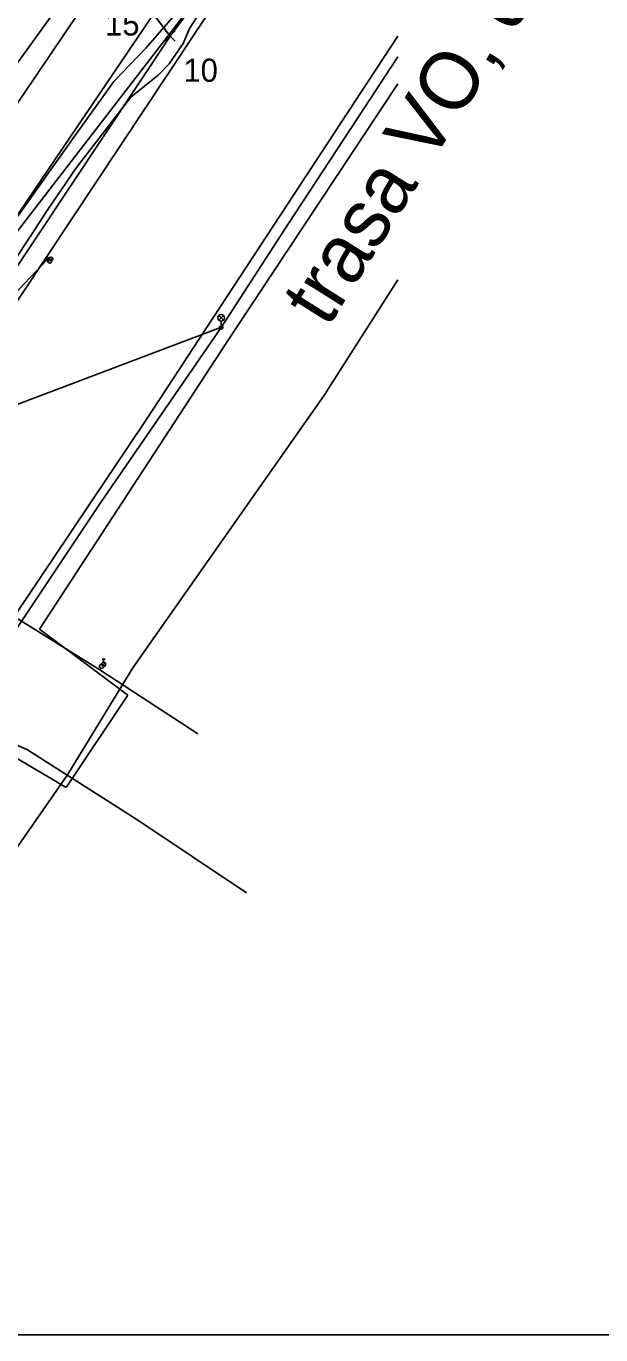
# Model space of a CAD drawing. Extents: x -263861 to -263441, y -1242367 to -1242070.
# Drawn here: x -263782.2 to -263732.4, y -1242367.2 to -1242254.1 of the extents above; entities that cross this region are included whole.
import ezdxf

# ---------------------------------------------------------------- set-up
doc = ezdxf.new("R2010")
doc.units = 0
for name, color, linetype in [('KFA_BODY', 7, 'Continuous'), ('KFA_JESTV_IS_DSP', 7, 'Continuous'), ('KFA_SITUACIA_DSP', 7, 'Continuous'), ('KFA_VO_prelozka_pri_vjazde_do KFA_TRASA', 7, 'Continuous'), ('POPIS', 7, 'Continuous'), ('RAM_NA_TLAC_A3_1-1000', 7, 'Continuous')]:
    doc.layers.add(name, color=color, linetype=linetype)

msp = doc.modelspace()

# ---------------------------------------------------------------- linework, layer by layer
at = {"layer": 'KFA_BODY'}
for p, q in [((-263770.14, -1242255.37), (-263769.26, -1242254.48)), ((-263769.26, -1242255.37), (-263770.14, -1242254.48)), ((-263769.7, -1242254.93), (-263769.7, -1242254.93))]:
    msp.add_line(p, q, dxfattribs=at)
at = {"layer": 'KFA_JESTV_IS_DSP'}
for p, q in [((-263806.91, -1242290.43), (-263750, -1242211.71)), ((-263766.13, -1242251.37), (-263768.04, -1242254.28)), ((-263771.82, -1242255.98), (-263768.68, -1242252.39)), ((-263768.04, -1242254.28), (-263768.58, -1242255.58)), ((-263750, -1242254.94), (-263754.37, -1242261.56)), ((-263774.57, -1242258.86), (-263771.82, -1242255.98)), ((-263768.58, -1242255.58), (-263769.79, -1242257.33)), ((-263769.79, -1242257.33), (-263770.75, -1242258.31)), ((-263750, -1242256.71), (-263759.47, -1242271.14)), ((-263777.94, -1242263.54), (-263774.57, -1242258.86)), ((-263770.75, -1242258.31), (-263773.12, -1242260.22)), ((-263764.86, -1242281.49), (-263750, -1242259.06)), ((-263773.12, -1242260.22), (-263777.8, -1242266.3)), ((-263754.37, -1242261.56), (-263771.77, -1242288.1)), ((-263781.56, -1242268.62), (-263777.94, -1242263.54)), ((-263777.8, -1242266.3), (-263780.3, -1242269.92)), ((-263784.91, -1242273.31), (-263781.56, -1242268.62)), ((-263780.3, -1242269.92), (-263790.03, -1242284.82)), ((-263759.47, -1242271.14), (-263765.29, -1242280.13)), ((-263756.19, -1242285.72), (-263750, -1242276.01)), ((-263765.49, -1242279.09), (-263765.09, -1242279.49)), ((-263765.09, -1242279.09), (-263765.49, -1242279.49)), ((-263792.97, -1242290.55), (-263765.27, -1242280.1)), ((-263765.29, -1242280.13), (-263775.66, -1242295.19)), ((-263765.29, -1242279.57), (-263765.29, -1242280.13)), ((-263781.01, -1242306.2), (-263764.86, -1242281.49)), ((-263772.92, -1242309.53), (-263756.2, -1242285.74)), ((-263756.2, -1242285.73), (-263756.19, -1242285.72)), ((-263756.2, -1242285.74), (-263756.2, -1242285.73)), ((-263771.77, -1242288.1), (-263786.26, -1242309.66)), ((-263806.91, -1242290.43), (-263775.78, -1242309.71)), ((-263775.66, -1242295.19), (-263784.7, -1242308.69)), ((-263773.36, -1242311.9), (-263781.01, -1242306.2)), ((-263778.59, -1242318.79), (-263772.92, -1242309.53)), ((-263775.78, -1242309.71), (-263767.31, -1242315.26)), ((-263775.61, -1242309.35), (-263775.31, -1242309.12)), ((-263775.58, -1242308.8), (-263775.33, -1242308.8)), ((-263775.46, -1242309.05), (-263775.46, -1242308.8)), ((-263778.69, -1242319.9), (-263773.36, -1242311.9)), ((-263786.42, -1242314.72), (-263782.04, -1242316.62)), ((-263785.11, -1242316.11), (-263778.69, -1242319.9)), ((-263782.04, -1242316.62), (-263772.58, -1242322.66)), ((-263778.59, -1242318.79), (-263795.54, -1242343.13)), ((-263772.58, -1242322.66), (-263763.1, -1242328.99))]:
    msp.add_line(p, q, dxfattribs=at)
for centre, radius in [((-263765.29, -1242279.29), 0.281), ((-263765.29, -1242280.13), 0.15), ((-263775.64, -1242309.41), 0.179), ((-263775.46, -1242309.24), 0.188)]:
    msp.add_circle(centre, radius, dxfattribs=at)
at = {"layer": 'KFA_SITUACIA_DSP'}
for p, q in [((-263822.88, -1242337.91), (-263734.49, -1242204.94)), ((-263794.9, -1242288.03), (-263742.74, -1242211.14)), ((-263798.9, -1242284.13), (-263751.86, -1242215.08)), ((-263752.52, -1242232.37), (-263782.17, -1242270.82)), ((-263780.35, -1242274.24), (-263808.25, -1242303.78)), ((-263780.34, -1242274.43), (-263780.06, -1242274.01)), ((-263780.06, -1242274.01), (-263780.34, -1242274.43)), ((-263780.34, -1242274.43), (-263779.82, -1242274.17)), ((-263780.34, -1242274.43), (-263779.82, -1242274.17)), ((-263780.1, -1242274.59), (-263780.34, -1242274.43)), ((-263779.82, -1242274.17), (-263780.1, -1242274.59)), ((-263780.06, -1242274.01), (-263779.82, -1242274.17)), ((-263779.82, -1242274.17), (-263780.06, -1242274.01))]:
    msp.add_line(p, q, dxfattribs=at)
msp.add_circle((-263780.28, -1242274.16), 0.1, dxfattribs=at)
msp.add_arc((-263742.57, -1242301.35), 50, 142.3688, 146.3992, dxfattribs=at)
at = {"layer": 'KFA_VO_prelozka_pri_vjazde_do KFA_TRASA'}
msp.add_line((-263771.53, -1242252.55), (-263769.7, -1242254.93), dxfattribs=at)
msp.add_lwpolyline([(-263678.35, -1242101.42), (-263696.56, -1242141.18), (-263711.21, -1242160.53), (-263718.89, -1242173.72), (-263725.97, -1242184.27), (-263742.99, -1242211.9), (-263755.73, -1242230.93), (-263756.36, -1242233.15), (-263759.75, -1242241.52), (-263769.7, -1242254.93), (-263792.51, -1242289.19), (-263819.79, -1242330.66), (-263820.54, -1242331.86)], dxfattribs=at)
at = {"layer": 'RAM_NA_TLAC_A3_1-1000'}
msp.add_lwpolyline([(-263861.44, -1242070.21), (-263441.44, -1242070.21), (-263441.44, -1242367.21), (-263861.44, -1242367.21)], close=True, dxfattribs=at)

# ---------------------------------------------------------------- texts
at = {"layer": 'KFA_BODY'}
for s, p in [('15', (-263775.33, -1242254.88)), ('10', (-263768.55, -1242258.88))]:
    msp.add_text(s, height=2, dxfattribs=at).set_placement(p)
at = {"layer": 'POPIS'}
msp.add_text('trasa VO, dĺžka preložky - 271,57 m', height=5, rotation=57.838, dxfattribs=at).set_placement((-263756.08, -1242280.23))

doc.saveas('drawing.dxf')
